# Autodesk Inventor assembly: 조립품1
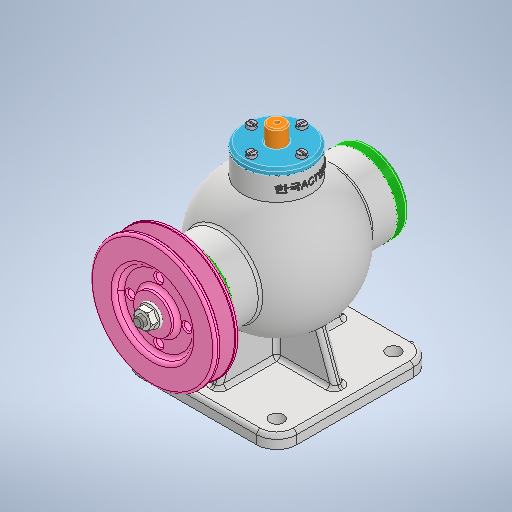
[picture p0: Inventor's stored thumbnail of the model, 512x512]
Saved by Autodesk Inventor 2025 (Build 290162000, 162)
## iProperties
Created: 2024-07
Part Number: 조립품1
Document SubType Name: Assembly
Designer: samsung
Author: samsung
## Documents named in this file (14)
- C:\Users\samsung\Desktop\740708V1012\조립품1.iam
- C:\Users\samsung\Desktop\740708V1012\본체1.ipt
- C:\Users\samsung\Desktop\740708V1012\베어링- 6202\베어링- 6202.ipt
- C:\Users\samsung\Desktop\740708V1012\뒤커버\뒤커버.ipt
- C:\Users\samsung\Desktop\740708V1012\칼라\칼라.ipt
- C:\Users\samsung\Desktop\740708V1012\편심축\편심축.ipt
- C:\Users\samsung\Desktop\740708V1012\앞커버\앞커버.ipt
- C:\Users\samsung\Desktop\740708V1012\키 4 x 4 x 12\키 4 x 4 x 12.ipt
- C:\Users\samsung\Desktop\740708V1012\V-벨트풀리\V-벨트풀리.ipt
- C:\Users\samsung\Desktop\740708V1012\너트 M8\너트 M8.ipt
- C:\Users\samsung\Desktop\740708V1012\슬라이드\슬라이드.ipt
- C:\Users\samsung\Desktop\740708V1012\상부커버\상부커버.ipt
- C:\Users\samsung\Desktop\740708V1012\볼트 M4 x 16\볼트 M4 x 16.ipt
- C:\Users\samsung\Desktop\740708V1012\볼트 M4 x 12\볼트 M4 x 12.ipt
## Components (1 placed, 1 different names)
1. V-벨트풀리:1 — 각도:3
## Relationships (1: Angle 1)
- 각도:3 [Angle]: V-벨트풀리:1
